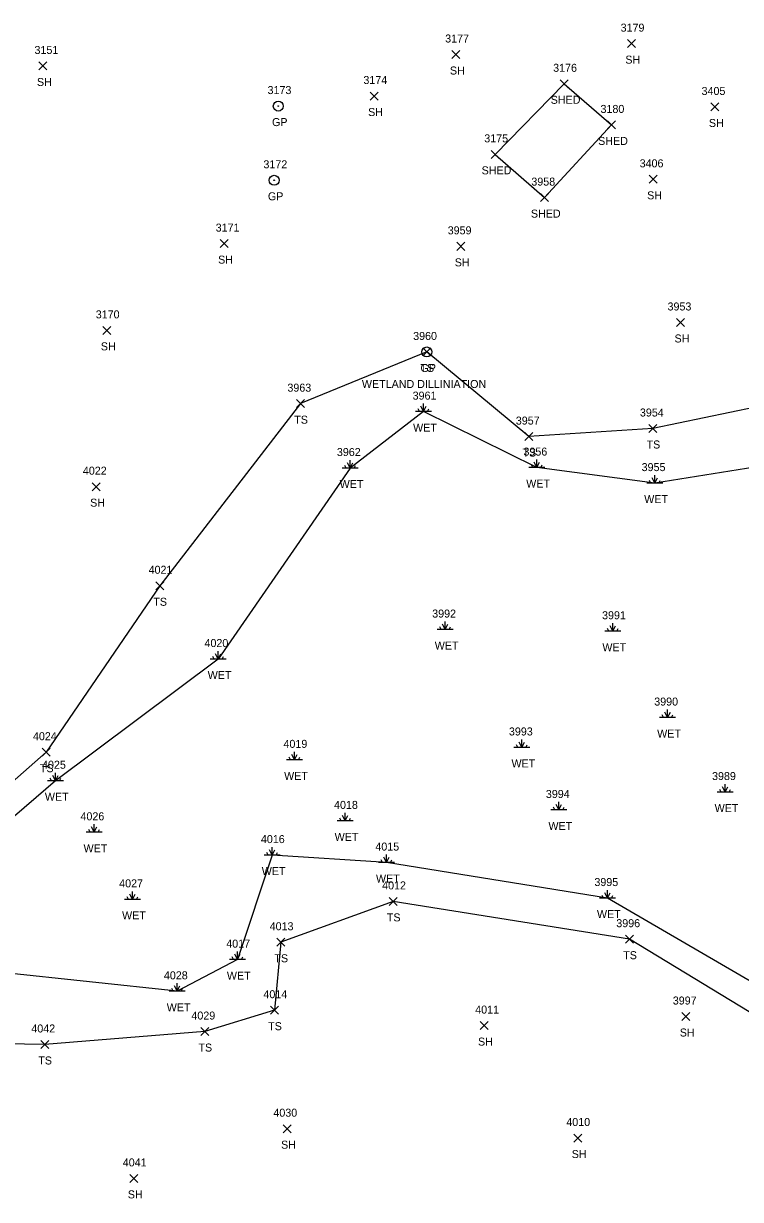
# Model space of a CAD drawing. Extents: x 1472233 to 1475777, y 540726 to 543442.
# Drawn here: x 1473901.5 to 1474080.6, y 541777 to 542070.9 of the extents above; entities that cross this region are included whole.
import ezdxf

# ---------------------------------------------------------------- set-up
doc = ezdxf.new("R2010")
doc.units = 0
for name, color, linetype in [('L_A', 7, 'Continuous'), ('L_I', 7, 'Continuous'), ('L_TIC', 7, 'Continuous'), ('LBC', 7, 'Continuous'), ('LELB', 7, 'Continuous'), ('LWET', 7, 'Continuous'), ('R_A', 7, 'Continuous'), ('R_C', 7, 'Continuous'), ('R_I', 7, 'Continuous'), ('RGP', 7, 'Continuous')]:
    doc.layers.add(name, color=color, linetype=linetype)

msp = doc.modelspace()

# ---------------------------------------------------------------- linework, layer by layer
at = {"layer": 'L_TIC'}
for points in [[(1474052.33, 542064.91), (1474054.33, 542066.91)], [(1474054.33, 542064.91), (1474052.33, 542066.91)], [(1474008.5, 542062.19), (1474010.5, 542064.19)], [(1474010.5, 542062.19), (1474008.5, 542064.19)], [(1473905.35, 542059.33), (1473907.35, 542061.33)], [(1473907.35, 542059.33), (1473905.35, 542061.33)], [(1474035.52, 542054.87), (1474037.52, 542056.87)], [(1474037.52, 542054.87), (1474035.52, 542056.87)], [(1473988.07, 542051.82), (1473990.07, 542053.82)], [(1473990.07, 542051.82), (1473988.07, 542053.82)], [(1474073.19, 542049.08), (1474075.19, 542051.08)], [(1474075.19, 542049.08), (1474073.19, 542051.08)], [(1474047.39, 542044.59), (1474049.39, 542046.59)], [(1474049.39, 542044.59), (1474047.39, 542046.59)], [(1474018.27, 542037.23), (1474020.27, 542039.23)], [(1474020.27, 542037.23), (1474018.27, 542039.23)], [(1474018.27, 542037.23), (1474020.27, 542039.23)], [(1474020.27, 542037.23), (1474018.27, 542039.23)], [(1474057.77, 542030.99), (1474059.77, 542032.99)], [(1474059.77, 542030.99), (1474057.77, 542032.99)], [(1474030.59, 542026.42), (1474032.59, 542028.42)], [(1474032.59, 542026.42), (1474030.59, 542028.42)], [(1474030.59, 542026.42), (1474032.59, 542028.42)], [(1474032.59, 542026.42), (1474030.59, 542028.42)], [(1473950.6, 542014.92), (1473952.6, 542016.92)], [(1473952.6, 542014.92), (1473950.6, 542016.92)], [(1474009.71, 542014.24), (1474011.71, 542016.24)], [(1474011.71, 542014.24), (1474009.71, 542016.24)], [(1474064.61, 541995.21), (1474066.61, 541997.21)], [(1474066.61, 541995.21), (1474064.61, 541997.21)], [(1473921.31, 541993.23), (1473923.31, 541995.23)], [(1473923.31, 541993.23), (1473921.31, 541995.23)], [(1474001.21, 541987.83), (1474003.21, 541989.83)], [(1474003.21, 541987.83), (1474001.21, 541989.83)], [(1473969.7, 541974.91), (1473971.7, 541976.91)], [(1473971.7, 541974.91), (1473969.7, 541976.91)], [(1474057.71, 541968.7), (1474059.71, 541970.7)], [(1474059.71, 541968.7), (1474057.71, 541970.7)], [(1474026.71, 541966.68), (1474028.71, 541968.68)], [(1474028.71, 541966.68), (1474026.71, 541968.68)], [(1473918.64, 541954.16), (1473920.64, 541956.16)], [(1473920.64, 541954.16), (1473918.64, 541956.16)], [(1473934.5, 541929.39), (1473936.5, 541931.39)], [(1473936.5, 541929.39), (1473934.5, 541931.39)], [(1473906.17, 541887.78), (1473908.17, 541889.78)], [(1473908.17, 541887.78), (1473906.17, 541889.78)], [(1473992.83, 541850.49), (1473994.83, 541852.49)], [(1473994.83, 541850.49), (1473992.83, 541852.49)], [(1474051.87, 541841.04), (1474053.87, 541843.04)], [(1474053.87, 541841.04), (1474051.87, 541843.04)], [(1473964.74, 541840.27), (1473966.74, 541842.27)], [(1473966.74, 541840.27), (1473964.74, 541842.27)], [(1473963.18, 541823.29), (1473965.18, 541825.29)], [(1473965.18, 541823.29), (1473963.18, 541825.29)], [(1474065.92, 541821.71), (1474067.92, 541823.71)], [(1474067.92, 541821.71), (1474065.92, 541823.71)], [(1473945.77, 541817.95), (1473947.77, 541819.95)], [(1473947.77, 541817.95), (1473945.77, 541819.95)], [(1474015.52, 541819.44), (1474017.52, 541821.44)], [(1474017.52, 541819.44), (1474015.52, 541821.44)], [(1473905.78, 541814.72), (1473907.78, 541816.72)], [(1473907.78, 541814.72), (1473905.78, 541816.72)], [(1473966.33, 541793.67), (1473968.33, 541795.67)], [(1473968.33, 541793.67), (1473966.33, 541795.67)], [(1474038.93, 541791.34), (1474040.93, 541793.34)], [(1474040.93, 541791.34), (1474038.93, 541793.34)], [(1473928.06, 541781.24), (1473930.06, 541783.24)], [(1473930.06, 541781.24), (1473928.06, 541783.24)]]:
    msp.add_lwpolyline(points, dxfattribs=at)
at = {"layer": 'LBC'}
for points in [[(1474019.27, 542038.23), (1474036.52, 542055.87), (1474048.39, 542045.59), (1474031.59, 542027.42)], [(1474019.27, 542038.23), (1474031.59, 542027.42)]]:
    msp.add_lwpolyline(points, dxfattribs=at)
at = {"layer": 'LELB'}
for points in [[(1474084.3, 541975.02), (1474058.71, 541969.7), (1474027.71, 541967.68), (1474002.21, 541988.83), (1473970.7, 541975.91), (1473935.5, 541930.39), (1473907.17, 541888.78), (1473878.03, 541863.11), (1473834.25, 541860.01), (1473797.64, 541834.14), (1473756.71, 541810.03), (1473674.57, 541798.94)], [(1474197.62, 541783.9), (1474176.1, 541761.24), (1474128.91, 541795.8), (1474052.87, 541842.04), (1473993.83, 541851.49), (1473965.74, 541841.27), (1473964.18, 541824.29), (1473946.77, 541818.95), (1473906.78, 541815.72), (1473855.67, 541816.56), (1473816.66, 541810.89), (1473771.41, 541788.95), (1473709.93, 541752.76)]]:
    msp.add_lwpolyline(points, dxfattribs=at)
at = {"layer": 'LWET'}
for p, q in [((1474001.42, 541973.92), (1474000.75, 541975.25)), ((1474001.42, 541973.92), (1474001.42, 541975.92)), ((1474001.42, 541973.92), (1474002.08, 541975.25)), ((1474003.42, 541973.92), (1473999.42, 541973.92)), ((1474000.42, 541973.92), (1474000.08, 541974.58)), ((1474002.42, 541973.92), (1474002.75, 541974.58)), ((1473982.07, 541959.82), (1473981.73, 541960.48)), ((1473983.07, 541959.82), (1473982.4, 541961.15)), ((1473983.07, 541959.82), (1473983.07, 541961.82)), ((1473983.07, 541959.82), (1473983.73, 541961.15)), ((1473984.07, 541959.82), (1473984.4, 541960.48)), ((1474028.67, 541959.93), (1474028.34, 541960.59)), ((1474029.67, 541959.93), (1474029.01, 541961.26)), ((1474029.67, 541959.93), (1474029.67, 541961.93)), ((1474029.67, 541959.93), (1474030.34, 541961.26)), ((1474030.67, 541959.93), (1474031.01, 541960.59)), ((1473985.07, 541959.82), (1473981.07, 541959.82)), ((1474031.67, 541959.93), (1474027.67, 541959.93)), ((1474059.14, 541956.05), (1474058.47, 541957.38)), ((1474059.14, 541956.05), (1474059.14, 541958.05)), ((1474059.14, 541956.05), (1474059.81, 541957.38)), ((1474061.14, 541956.05), (1474057.14, 541956.05)), ((1474058.14, 541956.05), (1474057.81, 541956.71)), ((1474060.14, 541956.05), (1474060.47, 541956.71)), ((1474008.83, 541919.44), (1474004.83, 541919.44)), ((1474005.83, 541919.44), (1474005.49, 541920.11)), ((1474006.83, 541919.44), (1474006.16, 541920.77)), ((1474006.83, 541919.44), (1474006.83, 541921.44)), ((1474006.83, 541919.44), (1474007.49, 541920.77)), ((1474007.83, 541919.44), (1474008.16, 541920.11)), ((1474050.69, 541919.02), (1474046.69, 541919.02)), ((1474047.69, 541919.02), (1474047.36, 541919.68)), ((1474048.69, 541919.02), (1474048.03, 541920.35)), ((1474048.69, 541919.02), (1474048.69, 541921.02)), ((1474048.69, 541919.02), (1474049.36, 541920.35)), ((1474049.69, 541919.02), (1474050.03, 541919.68)), ((1473950.12, 541912.07), (1473949.45, 541913.4)), ((1473950.12, 541912.07), (1473950.12, 541914.07)), ((1473950.12, 541912.07), (1473950.78, 541913.4)), ((1473952.12, 541912.07), (1473948.12, 541912.07)), ((1473949.12, 541912.07), (1473948.78, 541912.74)), ((1473951.12, 541912.07), (1473951.45, 541912.74)), ((1474062.38, 541897.44), (1474061.71, 541898.77)), ((1474062.38, 541897.44), (1474062.38, 541899.44)), ((1474062.38, 541897.44), (1474063.05, 541898.77)), ((1474064.38, 541897.44), (1474060.38, 541897.44)), ((1474061.38, 541897.44), (1474061.05, 541898.11)), ((1474063.38, 541897.44), (1474063.71, 541898.11)), ((1474027.99, 541889.97), (1474023.99, 541889.97)), ((1474024.99, 541889.97), (1474024.66, 541890.63)), ((1474025.99, 541889.97), (1474025.32, 541891.3)), ((1474025.99, 541889.97), (1474025.99, 541891.97)), ((1474025.99, 541889.97), (1474026.66, 541891.3)), ((1474026.99, 541889.97), (1474027.32, 541890.63)), ((1473971.2, 541886.87), (1473967.2, 541886.87)), ((1473968.2, 541886.87), (1473967.87, 541887.54)), ((1473969.2, 541886.87), (1473968.54, 541888.21)), ((1473969.2, 541886.87), (1473969.2, 541888.87)), ((1473969.2, 541886.87), (1473969.87, 541888.21)), ((1473970.2, 541886.87), (1473970.54, 541887.54)), ((1473911.45, 541881.65), (1473907.45, 541881.65)), ((1473908.45, 541881.65), (1473908.11, 541882.31)), ((1473909.45, 541881.65), (1473908.78, 541882.98)), ((1473909.45, 541881.65), (1473909.45, 541883.65)), ((1473909.45, 541881.65), (1473910.11, 541882.98)), ((1473910.45, 541881.65), (1473910.78, 541882.31)), ((1474076.73, 541878.82), (1474076.73, 541880.82)), ((1474078.73, 541878.82), (1474074.73, 541878.82)), ((1474075.73, 541878.82), (1474075.4, 541879.49)), ((1474076.73, 541878.82), (1474076.07, 541880.16)), ((1474076.73, 541878.82), (1474077.4, 541880.16)), ((1474077.73, 541878.82), (1474078.07, 541879.49)), ((1474034.22, 541874.34), (1474033.89, 541875.01)), ((1474035.22, 541874.34), (1474034.56, 541875.67)), ((1474035.22, 541874.34), (1474035.22, 541876.34)), ((1474035.22, 541874.34), (1474035.89, 541875.67)), ((1474036.22, 541874.34), (1474036.56, 541875.01)), ((1473980.82, 541871.61), (1473980.49, 541872.28)), ((1473981.82, 541871.61), (1473981.15, 541872.95)), ((1473981.82, 541871.61), (1473981.82, 541873.61)), ((1473981.82, 541871.61), (1473982.49, 541872.95)), ((1473982.82, 541871.61), (1473983.15, 541872.28)), ((1474037.22, 541874.34), (1474033.22, 541874.34)), ((1473918.1, 541868.76), (1473917.77, 541869.42)), ((1473919.1, 541868.76), (1473918.44, 541870.09)), ((1473919.1, 541868.76), (1473919.1, 541870.76)), ((1473919.1, 541868.76), (1473919.77, 541870.09)), ((1473920.1, 541868.76), (1473920.44, 541869.42)), ((1473983.82, 541871.61), (1473979.82, 541871.61)), ((1473921.1, 541868.76), (1473917.1, 541868.76)), ((1473962.61, 541863.06), (1473962.28, 541863.73)), ((1473963.61, 541863.06), (1473962.94, 541864.4)), ((1473963.61, 541863.06), (1473963.61, 541865.06)), ((1473963.61, 541863.06), (1473964.28, 541864.4)), ((1473964.61, 541863.06), (1473964.94, 541863.73)), ((1473992.14, 541861.19), (1473992.14, 541863.19)), ((1473965.61, 541863.06), (1473961.61, 541863.06)), ((1473994.14, 541861.19), (1473990.14, 541861.19)), ((1473991.14, 541861.19), (1473990.81, 541861.86)), ((1473992.14, 541861.19), (1473991.47, 541862.52)), ((1473992.14, 541861.19), (1473992.81, 541862.52)), ((1473993.14, 541861.19), (1473993.47, 541861.86)), ((1474047.34, 541852.32), (1474047.34, 541854.32)), ((1473930.72, 541852), (1473926.72, 541852)), ((1473927.72, 541852), (1473927.39, 541852.66)), ((1473928.72, 541852), (1473928.05, 541853.33)), ((1473928.72, 541852), (1473928.72, 541854)), ((1473928.72, 541852), (1473929.39, 541853.33)), ((1473929.72, 541852), (1473930.05, 541852.66)), ((1474049.34, 541852.32), (1474045.34, 541852.32)), ((1474046.34, 541852.32), (1474046.01, 541852.98)), ((1474047.34, 541852.32), (1474046.68, 541853.65)), ((1474047.34, 541852.32), (1474048.01, 541853.65)), ((1474048.34, 541852.32), (1474048.68, 541852.98)), ((1473956.9, 541836.93), (1473952.9, 541836.93)), ((1473953.9, 541836.93), (1473953.57, 541837.59)), ((1473954.9, 541836.93), (1473954.24, 541838.26)), ((1473954.9, 541836.93), (1473954.9, 541838.93)), ((1473954.9, 541836.93), (1473955.57, 541838.26)), ((1473955.9, 541836.93), (1473956.24, 541837.59)), ((1473939.89, 541829.01), (1473939.89, 541831.01)), ((1473941.89, 541829.01), (1473937.89, 541829.01)), ((1473938.89, 541829.01), (1473938.55, 541829.68)), ((1473939.89, 541829.01), (1473939.22, 541830.34)), ((1473939.89, 541829.01), (1473940.55, 541830.34)), ((1473940.89, 541829.01), (1473941.22, 541829.68))]:
    msp.add_line(p, q, dxfattribs=at)
for points in [[(1474201.28, 541999.97), (1474193.13, 541997.3), (1474187.4, 541993.72), (1474190.5, 541975.23), (1474161.66, 541948.69), (1474141.28, 541938.83), (1474117.83, 541934.72), (1474098.62, 541941.34), (1474084.19, 541960.07), (1474059.14, 541956.05), (1474029.67, 541959.93), (1474001.42, 541973.92), (1473983.07, 541959.82), (1473950.12, 541912.07), (1473909.45, 541881.65), (1473881.64, 541857.75), (1473838.87, 541852.45), (1473801.01, 541830.26), (1473760.94, 541803.25), (1473684.41, 541785.97)], [(1474298.24, 541830.53), (1474275.06, 541794.79), (1474251.71, 541789.09), (1474197.62, 541783.9), (1474168.8, 541779.15), (1474131.77, 541803.11), (1474047.34, 541852.32), (1473992.14, 541861.19), (1473963.61, 541863.06), (1473954.9, 541836.93), (1473939.89, 541829.01), (1473896.04, 541833.75), (1473853.46, 541825.22), (1473812.5, 541815.77), (1473769.07, 541792.78), (1473703.23, 541762.05)]]:
    msp.add_lwpolyline(points, dxfattribs=at)
at = {"layer": 'RGP'}
for p, q in [((1473965.13, 542050.3), (1473965.13, 542050.3)), ((1473964.1, 542031.75), (1473964.1, 542031.75)), ((1474002.21, 541988.83), (1474002.21, 541988.83))]:
    msp.add_line(p, q, dxfattribs=at)
for centre, radius in [((1473965.13, 542050.3), 1.25), ((1473965.13, 542050.3), 0.0833), ((1473964.1, 542031.75), 1.25), ((1473964.1, 542031.75), 0.0833), ((1474002.21, 541988.83), 1.25), ((1474002.21, 541988.83), 0.0833)]:
    msp.add_circle(centre, radius, dxfattribs=at)

# ---------------------------------------------------------------- texts
at = {"layer": 'L_A'}
for s, p in [('SH', (1474007.99, 542058.19)), ('SH', (1474051.81, 542060.91)), ('SH', (1473904.84, 542055.33)), ('SHED', (1474033.16, 542050.87)), ('SH', (1473987.56, 542047.82)), ('SH', (1474072.68, 542045.08)), ('SHED', (1474045.02, 542040.59)), ('SHED', (1474015.91, 542033.23)), ('SHED', (1474015.91, 542033.23)), ('SH', (1474057.26, 542026.99)), ('SHED', (1474028.22, 542022.42)), ('SHED', (1474028.22, 542022.42)), ('SH', (1473950.09, 542010.92)), ('SH', (1474009.2, 542010.24)), ('SH', (1474064.1, 541991.21)), ('SH', (1473920.8, 541989.23)), ('TS', (1474000.62, 541983.83)), ('TS', (1473969.11, 541970.91)), ('WET', (1473998.79, 541968.92)), ('TS', (1474057.12, 541964.7)), ('TS', (1474026.12, 541962.68)), ('WET', (1473980.45, 541954.82)), ('WET', (1474027.05, 541954.93)), ('SH', (1473918.13, 541950.16)), ('WET', (1474056.52, 541951.05)), ('TS', (1473933.91, 541925.39)), ('WET', (1474004.2, 541914.44)), ('WET', (1474046.07, 541914.02)), ('WET', (1473947.49, 541907.07)), ('WET', (1474059.76, 541892.44)), ('WET', (1474023.37, 541884.97)), ('TS', (1473905.58, 541883.78)), ('WET', (1473966.58, 541881.87)), ('WET', (1473906.82, 541876.65)), ('WET', (1474074.11, 541873.82)), ('WET', (1474032.6, 541869.34)), ('WET', (1473979.2, 541866.61)), ('WET', (1473916.48, 541863.76)), ('WET', (1473960.99, 541858.06)), ('WET', (1473989.52, 541856.19)), ('WET', (1473926.1, 541847)), ('TS', (1473992.24, 541846.49)), ('WET', (1474044.72, 541847.32)), ('TS', (1473964.15, 541836.27)), ('TS', (1474051.28, 541837.04)), ('WET', (1473952.28, 541831.93)), ('WET', (1473937.26, 541824.01)), ('TS', (1473962.59, 541819.29)), ('SH', (1474065.41, 541817.71)), ('SH', (1474015.01, 541815.44)), ('TS', (1473945.18, 541813.95)), ('TS', (1473905.18, 541810.72)), ('SH', (1473965.82, 541789.67)), ('SH', (1474038.42, 541787.34)), ('SH', (1473927.54, 541777.24))]:
    msp.add_text(s, height=2, dxfattribs=at).set_placement(p)
at = {"layer": 'L_I'}
for s, p in [('3179', (1474050.63, 542068.91)), ('3177', (1474006.81, 542066.19)), ('3151', (1473904.23, 542063.33)), ('3176', (1474033.78, 542058.87)), ('3174', (1473986.38, 542055.82)), ('3405', (1474070.85, 542053.08)), ('3180', (1474045.61, 542048.59)), ('3175', (1474016.57, 542041.23)), ('3175', (1474016.57, 542041.23)), ('3406', (1474055.38, 542034.99)), ('3958', (1474028.33, 542030.42)), ('3958', (1474028.33, 542030.42)), ('3171', (1473949.48, 542018.92)), ('3959', (1474007.44, 542018.24)), ('3170', (1473919.53, 541997.23)), ('3953', (1474062.35, 541999.21)), ('3960', (1473998.81, 541991.83)), ('3963', (1473967.4, 541978.91)), ('3961', (1473998.68, 541976.92)), ('3957', (1474024.45, 541970.68)), ('3954', (1474055.45, 541972.7)), ('3962', (1473979.76, 541962.82)), ('3956', (1474026.36, 541962.93)), ('4022', (1473916.31, 541958.16)), ('3955', (1474055.88, 541959.05)), ('4021', (1473932.73, 541933.39)), ('3992', (1474003.57, 541922.44)), ('3991', (1474046, 541922.02)), ('4020', (1473946.69, 541915.07)), ('3990', (1474059.03, 541900.44)), ('4024', (1473903.84, 541891.78)), ('3993', (1474022.73, 541892.97)), ('4019', (1473966.42, 541889.87)), ('4025', (1473906.11, 541884.65)), ('3989', (1474073.47, 541881.82)), ('3994', (1474031.96, 541877.34)), ('4018', (1473979.05, 541874.61)), ('4026', (1473915.71, 541871.76)), ('4016', (1473960.78, 541866.06)), ('4015', (1473989.37, 541864.19)), ('3995', (1474044.08, 541855.32)), ('4027', (1473925.38, 541855)), ('4012', (1473991.06, 541854.49)), ('4013', (1473962.97, 541844.27)), ('3996', (1474049.55, 541845.04)), ('4017', (1473952.13, 541839.93)), ('4028', (1473936.55, 541832.01)), ('4014', (1473961.41, 541827.29)), ('4011', (1474014.31, 541823.44)), ('3997', (1474063.66, 541825.71)), ('4029', (1473943.42, 541821.95)), ('4042', (1473903.44, 541818.72)), ('4030', (1473963.9, 541797.67)), ('4010', (1474037.07, 541795.34)), ('4041', (1473926.28, 541785.24))]:
    msp.add_text(s, height=2, dxfattribs=at).set_placement(p)
at = {"layer": 'R_A'}
for p in [(1473963.56, 542045.3), (1473962.53, 542026.75), (1474000.64, 541983.83)]:
    msp.add_text('GP', height=2, dxfattribs=at).set_placement(p)
at = {"layer": 'R_C'}
msp.add_text('WETLAND DILLINIATION', height=2, dxfattribs=at).set_placement((1473986, 541979.83))
at = {"layer": 'R_I'}
for s, p in [('3173', (1473962.44, 542053.3)), ('3172', (1473961.41, 542034.75)), ('3960', (1473998.81, 541991.83))]:
    msp.add_text(s, height=2, dxfattribs=at).set_placement(p)

doc.saveas('drawing.dxf')
